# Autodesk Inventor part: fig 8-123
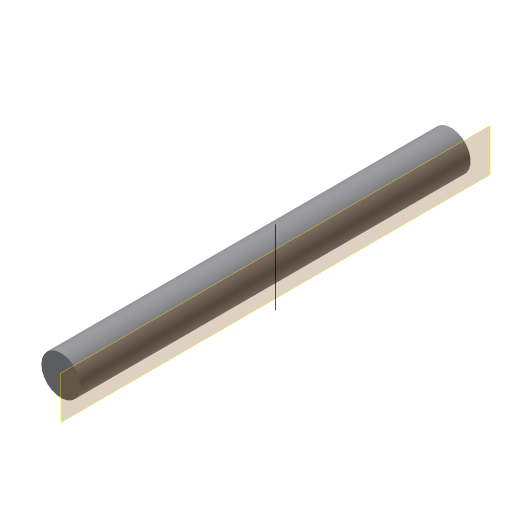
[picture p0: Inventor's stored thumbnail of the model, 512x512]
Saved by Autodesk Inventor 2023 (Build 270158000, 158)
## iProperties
Created: 2007-02
Part Number: fig 8-123
Document SubType Name: Modeling
Designer: Administrator
Density: 1 g/cm^3
Material: Generic
Appearance: Default
Author: Administrator
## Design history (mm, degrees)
node "Sketch1"
sketch "Sketch2"
  geometry: C1 r 5 at (0, 0); 1 further point
  constraints: 1 centre point, 1 coincident, 1 other
  dimensions: "d0" = 10 diameter of C1
extrude "Extrusion1" new body sketch "Sketch2" stored distance "d1" = 100; taper "d2" = 0 deg
workplane "Work Plane1"
sketch "Sketch3"
  geometry: L1 (0, 11)-(0, -8)
  constraints: 2 end point, 1 vertical
body "Solid1"
